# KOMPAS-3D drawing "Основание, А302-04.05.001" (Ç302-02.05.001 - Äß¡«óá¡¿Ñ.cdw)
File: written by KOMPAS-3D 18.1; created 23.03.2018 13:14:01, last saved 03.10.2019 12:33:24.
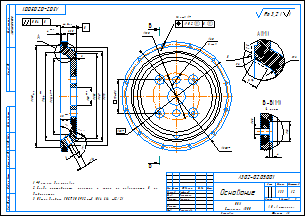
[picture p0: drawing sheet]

Sheet 1: A3, landscape

Document properties: Автор: Милов; Организация: Милов; Полное имя файла: D:\Мембранные насосы\Мембранный электропривод\А302-00.00.000 - ASTRA-302 (МЭ200)\Чертежи ПВХ\А302-02.05.001 - Основание.cdw; Параметр неуказанной шероховатости: Ra 3,2; Масса: 1.33374

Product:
- Part/product: Основание  | designation А302-04.05.001
    Материал: Полипропилен  ГОСТ 26996-86 (density 900 kg/m3)
    Масса: 1.33374
    Раздел спецификации: Детали
    Форматы листов документа: A3
- Part/product: Основание  | designation А302-00.05.001
    Материал: Полипропилен  ГОСТ 26996-86 (density 900 kg/m3)
    Масса: 1.33086
    Раздел спецификации: Детали
    Форматы листов документа: A3
    source file: \\192.168.87.28\Konstructor_doc\Мембранные насосы\Мембранный электропривод\А302-00.00.000 - ASTRA-302 (МЭ200)\Чертежи\А302-00.05.001 - Основание.cdw
- Part/product: Основание  | designation А302-03.05.001
    Материал: Полипропилен  ГОСТ 26996-86 (density 900 kg/m3)
    Масса: 1.33086
    Раздел спецификации: Детали
    Форматы листов документа: A3

Title block, sheet 1: Наименование: Основание; designation: А302-02.05.001; Материал: ПВХ / Стержень  300; Масса: 1,33; scale: 1:2; Количество листов документа: 1; organisation: АО «Астерион»; Форматы листов документа: A3; stored path: \\192.168.87.28\Konstructor_doc\Мембранные насосы\Мембранный электропривод\А302-00.00.000 - ASTRA-302 (МЭ200)\Чертежи\А302-00.05.001 - Основание.cdw; Разработал: Лифлянд; Проверил: Борисенко; Т. контр.: Лучихин; Утвердил: Григорьева

Views: Вид 1, Местный разрез 1, Вид:3, Проекционный вид 2, Выносной элемент 3, Разрез 4, Выносной элемент А, Выносной элемент
Referenced files in D:\Мембранные насосы\Мембранный электропривод\А302-00.00.000 - ASTRA-302 (МЭ200)\3Д\: А302-00.05.001 - Основание.m3d
Referenced files in Z:\Мембранные насосы\Мембранный электропривод\А302-00.00.000 - ASTRA-302 (МЭ200)\3Д\: А302-00.05.001 - Основание.m3d
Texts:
  Ra 3,2
  Ra 3,2 ( )
Dimensions and other numbers on the sheet: 16; 9; 50; 4; 44,5; 272; 28; 280; 211,67; 244; 0,04; 23,5; 247; 235; 2; 300; 20; 2 отв.; 130; 287; 12 отв.; 7; 92±0,2; 6; 12; 2,5; 15; 6 мест; 8,5; 1:2; 1; 1,33

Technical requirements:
  *Размеры для справок.
  Следы инструмента, царапины и риски на поверхности  В  не
  допускаются.
  Общие допуски ГОСТ 30893.2-mK (H14, h14,  t2/2).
